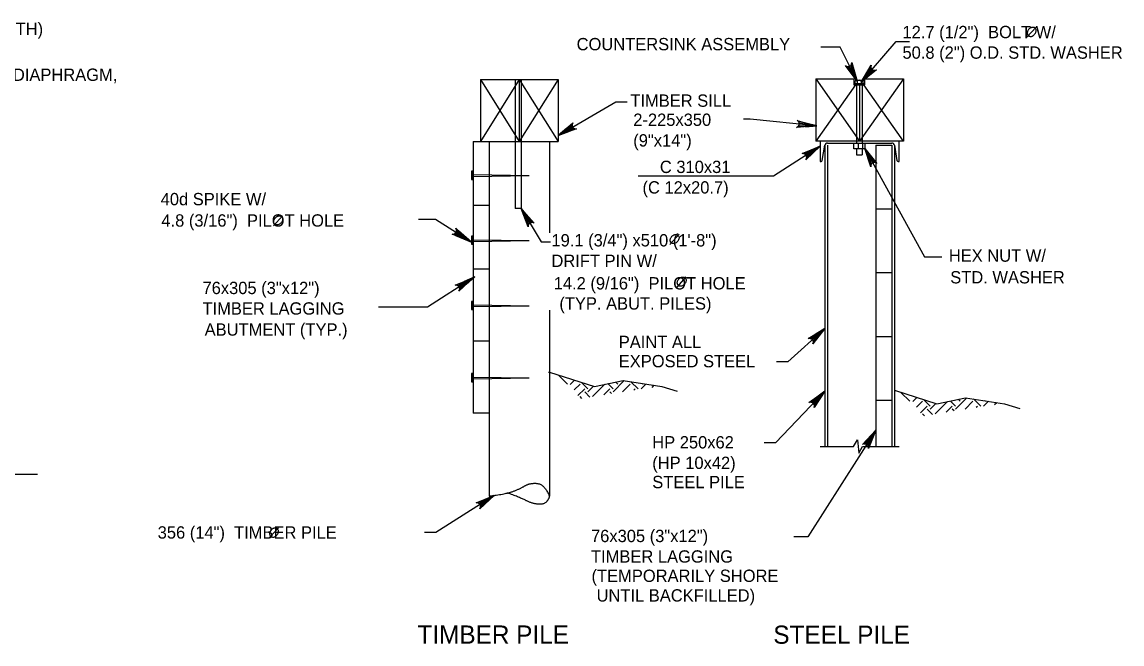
# Model space of a CAD drawing. Extents: x -13 to 81, y -176 to 0.
# Drawn here: x 47.78 to 58.49, y -37.68 to -31.62 of the extents above; entities that cross this region are included whole.
import ezdxf

# ---------------------------------------------------------------- set-up
doc = ezdxf.new("R2010")
doc.units = 0
for name, color, linetype in [('Level 3', 7, 'Continuous'), ('Level 4', 7, 'Continuous'), ('Level 5', 7, 'Continuous'), ('Level 52', 7, 'Continuous'), ('Level 8', 7, 'Continuous')]:
    doc.layers.add(name, color=color, linetype=linetype)

msp = doc.modelspace()

# ---------------------------------------------------------------- linework, layer by layer
at = {"layer": 'Level 3'}
for p, q in [((55.745, -31.865), (55.559, -31.865)), ((56.29, -31.812), (56.421, -31.812)), ((54.872, -32.566), (54.807, -32.566)), ((55.509, -32.633), (54.872, -32.566)), ((55.551, -32.831), (55.099, -33.124)), ((55.099, -33.124), (53.781, -33.124)), ((52.643, -33.438), (52.837, -33.762)), ((51.808, -33.545), (51.642, -33.545)), ((52.146, -33.758), (51.808, -33.545)), ((52.837, -33.762), (52.928, -33.762)), ((56.566, -33.908), (56.736, -33.908)), ((55.597, -35.217), (55.117, -35.72)), ((56.094, -35.597), (55.433, -36.635)), ((55.117, -35.72), (55.006, -35.72)), ((55.433, -36.635), (55.296, -36.635))]:
    msp.add_line(p, q, dxfattribs=at)
for points in [[(55.912, -32.197), (55.745, -31.865)], [(55.952, -32.208), (56.29, -31.812)], [(55.912, -32.197), (55.797, -32.046), (55.813, -32.054), (55.827, -32.056), (55.839, -32.052), (55.85, -32.044), (55.857, -32.032), (55.86, -32.015), (55.912, -32.197), (55.857, -32.032), (55.85, -32.044), (55.912, -32.197), (55.839, -32.052), (55.827, -32.056), (55.912, -32.197), (55.813, -32.054)], [(55.952, -32.208), (56.047, -32.043), (56.045, -32.06), (56.049, -32.074), (56.058, -32.084), (56.069, -32.09), (56.083, -32.093), (56.1, -32.088), (55.952, -32.208), (56.083, -32.093), (56.069, -32.09), (55.952, -32.208), (56.058, -32.084), (56.049, -32.074), (55.952, -32.208), (56.045, -32.06)], [(53.001, -32.727), (53.145, -32.602), (53.137, -32.618), (53.137, -32.633), (53.142, -32.645), (53.15, -32.654), (53.163, -32.661), (53.18, -32.663), (53.001, -32.727), (53.163, -32.661), (53.15, -32.654), (53.001, -32.727), (53.142, -32.645), (53.137, -32.633), (53.001, -32.727), (53.137, -32.618)], [(55.509, -32.633), (55.32, -32.649), (55.336, -32.64), (55.344, -32.628), (55.348, -32.616), (55.347, -32.604), (55.341, -32.59), (55.328, -32.579), (55.509, -32.633), (55.341, -32.59), (55.347, -32.604), (55.509, -32.633), (55.348, -32.616), (55.344, -32.628), (55.509, -32.633), (55.336, -32.64)], [(55.551, -32.831), (55.414, -32.962), (55.421, -32.946), (55.42, -32.931), (55.415, -32.919), (55.406, -32.91), (55.393, -32.904), (55.376, -32.903), (55.551, -32.831), (55.393, -32.904), (55.406, -32.91), (55.551, -32.831), (55.415, -32.919), (55.42, -32.931), (55.551, -32.831), (55.421, -32.946)], [(55.985, -32.852), (56.566, -33.908)], [(55.985, -32.852), (56.105, -32.998), (56.09, -32.99), (56.075, -32.99), (56.063, -32.994), (56.053, -33.002), (56.046, -33.014), (56.044, -33.032), (55.985, -32.852), (56.046, -33.014), (56.053, -33.002), (55.985, -32.852), (56.063, -32.994), (56.075, -32.99), (55.985, -32.852), (56.09, -32.99)], [(52.146, -33.758), (51.97, -33.689), (51.987, -33.688), (52, -33.681), (52.008, -33.672), (52.013, -33.66), (52.014, -33.645), (52.007, -33.629), (52.146, -33.758), (52.014, -33.645), (52.013, -33.66), (52.146, -33.758), (52.008, -33.672), (52, -33.681), (52.146, -33.758), (51.987, -33.688)], [(52.175, -34.112), (52.037, -34.243), (52.044, -34.227), (52.043, -34.212), (52.038, -34.201), (52.03, -34.191), (52.017, -34.185), (51.999, -34.184), (52.175, -34.112), (52.017, -34.185), (52.03, -34.191), (52.175, -34.112), (52.038, -34.201), (52.043, -34.212), (52.175, -34.112), (52.044, -34.227)], [(55.597, -34.605), (55.482, -34.756), (55.486, -34.739), (55.484, -34.725), (55.477, -34.714), (55.467, -34.706), (55.453, -34.702), (55.436, -34.704), (55.597, -34.605), (55.453, -34.702), (55.467, -34.706), (55.597, -34.605), (55.477, -34.714), (55.484, -34.725), (55.597, -34.605), (55.486, -34.739)], [(55.597, -35.217), (55.494, -35.376), (55.497, -35.359), (55.493, -35.345), (55.485, -35.334), (55.475, -35.327), (55.46, -35.324), (55.443, -35.328), (55.597, -35.217), (55.46, -35.324), (55.475, -35.327), (55.597, -35.217), (55.485, -35.334), (55.493, -35.345), (55.597, -35.217), (55.497, -35.359)], [(56.094, -35.597), (56.023, -35.773), (56.023, -35.755), (56.016, -35.742), (56.007, -35.734), (55.995, -35.729), (55.98, -35.728), (55.964, -35.735), (56.094, -35.597), (55.98, -35.728), (55.995, -35.729), (56.094, -35.597), (56.007, -35.734), (56.016, -35.742), (56.094, -35.597), (56.023, -35.755)], [(52.379, -36.231), (52.241, -36.361), (52.248, -36.345), (52.247, -36.33), (52.242, -36.319), (52.234, -36.309), (52.221, -36.303), (52.203, -36.302), (52.379, -36.231), (52.221, -36.303), (52.234, -36.309), (52.379, -36.231), (52.242, -36.319), (52.247, -36.33), (52.379, -36.231), (52.248, -36.345)]]:
    msp.add_lwpolyline(points, dxfattribs=at)
for points in [[(55.412, -32.605), (55.408, -32.641), (55.52, -32.634)], [(55.448, -32.876), (55.468, -32.907), (55.551, -32.831)], [(52.033, -33.654), (52.003, -33.701), (52.158, -33.766)], [(55.508, -35.284), (55.534, -35.31), (55.597, -35.217)], [(56.019, -35.68), (56.05, -35.7), (56.094, -35.597)]]:
    msp.add_lwpolyline(points, close=True, dxfattribs=at)
at = {"layer": 'Level 4'}
for p, q in [((57.564, -31.77), (57.654, -31.672)), ((50.232, -33.606), (50.321, -33.508)), ((54.09, -33.787), (54.179, -33.689)), ((54.159, -34.202), (54.248, -34.104)), ((50.191, -36.646), (50.281, -36.548))]:
    msp.add_line(p, q, dxfattribs=at)
for points in [[(57.644, -31.682), (57.637, -31.676), (57.63, -31.674), (57.622, -31.674), (57.616, -31.674), (57.608, -31.675), (57.6, -31.679), (57.594, -31.682), (57.584, -31.691), (57.576, -31.701), (57.571, -31.712), (57.568, -31.721), (57.567, -31.729), (57.568, -31.737), (57.571, -31.747), (57.575, -31.753), (57.583, -31.759), (57.594, -31.761), (57.608, -31.761), (57.624, -31.753), (57.636, -31.743), (57.646, -31.73), (57.652, -31.717), (57.654, -31.702), (57.651, -31.693), (57.645, -31.682)], [(50.312, -33.518), (50.305, -33.512), (50.298, -33.51), (50.289, -33.51), (50.284, -33.51), (50.276, -33.511), (50.268, -33.515), (50.262, -33.518), (50.252, -33.527), (50.243, -33.538), (50.238, -33.548), (50.235, -33.557), (50.234, -33.566), (50.235, -33.573), (50.239, -33.583), (50.243, -33.589), (50.25, -33.595), (50.262, -33.597), (50.275, -33.597), (50.292, -33.589), (50.304, -33.579), (50.313, -33.566), (50.319, -33.553), (50.321, -33.538), (50.319, -33.529), (50.312, -33.518)], [(54.17, -33.699), (54.163, -33.694), (54.156, -33.692), (54.147, -33.691), (54.142, -33.691), (54.133, -33.693), (54.125, -33.697), (54.12, -33.7), (54.109, -33.708), (54.101, -33.719), (54.096, -33.729), (54.093, -33.738), (54.092, -33.747), (54.093, -33.754), (54.097, -33.765), (54.101, -33.77), (54.108, -33.776), (54.12, -33.779), (54.133, -33.778), (54.15, -33.771), (54.162, -33.76), (54.171, -33.748), (54.177, -33.734), (54.179, -33.72), (54.177, -33.71), (54.17, -33.699)], [(54.239, -34.113), (54.232, -34.108), (54.225, -34.106), (54.216, -34.105), (54.211, -34.105), (54.203, -34.107), (54.194, -34.111), (54.189, -34.114), (54.178, -34.123), (54.17, -34.133), (54.165, -34.143), (54.162, -34.153), (54.161, -34.161), (54.162, -34.169), (54.166, -34.179), (54.17, -34.185), (54.177, -34.191), (54.189, -34.193), (54.202, -34.193), (54.219, -34.185), (54.231, -34.175), (54.24, -34.162), (54.246, -34.149), (54.248, -34.134), (54.246, -34.125), (54.239, -34.113)], [(50.271, -36.557), (50.264, -36.552), (50.257, -36.55), (50.249, -36.549), (50.243, -36.549), (50.235, -36.551), (50.227, -36.555), (50.221, -36.558), (50.211, -36.566), (50.203, -36.577), (50.198, -36.587), (50.195, -36.597), (50.194, -36.605), (50.195, -36.613), (50.198, -36.623), (50.202, -36.629), (50.21, -36.634), (50.221, -36.637), (50.235, -36.637), (50.251, -36.629), (50.264, -36.619), (50.273, -36.606), (50.279, -36.593), (50.281, -36.578), (50.278, -36.569), (50.272, -36.557)]]:
    msp.add_spline(points, degree=3, dxfattribs=at)
at = {"layer": 'Level 5'}
for p, q in [((52.245, -32.18), (53.001, -32.18)), ((52.246, -32.18), (52.246, -32.785)), ((52.623, -32.18), (52.246, -32.785)), ((52.246, -32.18), (52.623, -32.785)), ((52.585, -32.18), (52.585, -33.436)), ((52.623, -32.18), (53.001, -32.785)), ((53.001, -32.18), (52.623, -32.785)), ((52.623, -32.18), (52.623, -32.785)), ((52.643, -32.18), (52.643, -33.436)), ((53.001, -32.18), (53.001, -32.785)), ((55.509, -32.176), (55.935, -32.781)), ((55.509, -32.176), (55.509, -32.781)), ((55.509, -32.176), (55.664, -32.176)), ((55.509, -32.176), (55.881, -32.176)), ((55.881, -32.176), (55.881, -32.234)), ((55.881, -32.22), (55.985, -32.22)), ((55.892, -32.22), (55.892, -32.197)), ((55.962, -32.19), (55.902, -32.19)), ((55.912, -32.197), (55.912, -32.22)), ((56.362, -32.176), (55.935, -32.781)), ((55.952, -32.197), (55.952, -32.22)), ((55.971, -32.22), (55.971, -32.197)), ((55.985, -32.176), (56.362, -32.176)), ((56.362, -32.176), (56.362, -32.781)), ((55.895, -32.234), (55.509, -32.781)), ((55.904, -32.234), (55.904, -32.8)), ((55.935, -32.234), (55.935, -32.781)), ((55.962, -32.234), (55.962, -32.8)), ((56.362, -32.781), (55.977, -32.234)), ((53.001, -32.727), (53.564, -32.398)), ((53.564, -32.398), (53.675, -32.398)), ((52.175, -32.785), (52.175, -35.431)), ((52.175, -32.785), (52.33, -32.785)), ((52.246, -32.785), (53.001, -32.785)), ((52.33, -32.785), (52.33, -36.238)), ((52.917, -32.785), (52.917, -33.674)), ((56.362, -32.781), (55.509, -32.781)), ((55.551, -32.781), (55.551, -32.981)), ((55.572, -32.97), (55.597, -32.822)), ((55.597, -32.822), (55.597, -35.754)), ((55.623, -32.8), (56.248, -32.8)), ((55.623, -32.822), (55.623, -35.754)), ((55.904, -32.858), (55.904, -32.914)), ((55.925, -32.858), (55.925, -32.8)), ((55.962, -32.858), (55.962, -32.914)), ((55.968, -32.858), (55.968, -32.8)), ((56.094, -32.822), (56.094, -35.754)), ((56.094, -32.822), (56.249, -32.822)), ((56.249, -32.822), (56.249, -35.754)), ((56.274, -32.822), (56.274, -35.754)), ((56.274, -32.822), (56.299, -32.97)), ((56.32, -32.981), (56.32, -32.781)), ((55.904, -32.914), (55.962, -32.914)), ((55.551, -32.981), (55.56, -32.981)), ((56.312, -32.981), (56.32, -32.981)), ((52.175, -33.108), (52.72, -33.117)), ((52.175, -33.125), (52.72, -33.117)), ((52.175, -33.405), (52.33, -33.405)), ((52.643, -33.436), (52.585, -33.436)), ((56.094, -33.442), (56.249, -33.442)), ((52.175, -33.742), (52.72, -33.75)), ((52.175, -33.758), (52.72, -33.75)), ((52.175, -34.026), (52.33, -34.026)), ((52.175, -34.112), (51.732, -34.399)), ((56.094, -34.062), (56.249, -34.062)), ((51.732, -34.399), (51.254, -34.399)), ((52.175, -34.376), (52.72, -34.384)), ((52.175, -34.393), (52.72, -34.384)), ((52.917, -34.428), (52.917, -36.238)), ((55.597, -34.605), (55.237, -34.93)), ((56.094, -34.683), (56.249, -34.683)), ((52.33, -34.728), (52.175, -34.728)), ((55.237, -34.93), (55.126, -34.93)), ((52.175, -35.079), (52.72, -35.087)), ((52.175, -35.095), (52.72, -35.087)), ((53.092, -35.147), (53.005, -35.06)), ((53.12, -35.15), (53.161, -35.109)), ((53.157, -35.204), (53.215, -35.147)), ((53.194, -35.259), (53.261, -35.193)), ((53.291, -35.193), (53.229, -35.131)), ((53.291, -35.223), (53.346, -35.168)), ((53.337, -35.269), (53.457, -35.149)), ((53.446, -35.252), (53.505, -35.193)), ((53.536, -35.193), (53.486, -35.143)), ((53.536, -35.223), (53.646, -35.113)), ((53.582, -35.147), (53.562, -35.127)), ((53.629, -35.222), (53.704, -35.147)), ((53.78, -35.193), (53.711, -35.124)), ((53.738, -35.205), (53.75, -35.193)), ((53.809, -35.194), (53.857, -35.147)), ((53.826, -35.147), (53.82, -35.141)), ((53.917, -35.179), (53.936, -35.159)), ((53.233, -35.288), (53.215, -35.269)), ((53.312, -35.275), (53.261, -35.223)), ((53.521, -35.24), (53.505, -35.223)), ((56.094, -35.303), (56.249, -35.303)), ((56.425, -35.315), (56.338, -35.228)), ((56.453, -35.318), (56.494, -35.278)), ((56.49, -35.373), (56.548, -35.315)), ((56.624, -35.361), (56.562, -35.3)), ((56.67, -35.438), (56.79, -35.318)), ((56.869, -35.361), (56.819, -35.312)), ((56.869, -35.392), (56.979, -35.282)), ((56.915, -35.315), (56.895, -35.295)), ((56.962, -35.39), (57.037, -35.315)), ((57.114, -35.361), (57.044, -35.292)), ((57.143, -35.363), (57.19, -35.315)), ((57.16, -35.315), (57.153, -35.309)), ((52.33, -35.431), (52.175, -35.431)), ((56.527, -35.427), (56.594, -35.361)), ((56.645, -35.443), (56.594, -35.392)), ((56.624, -35.392), (56.679, -35.337)), ((56.779, -35.421), (56.838, -35.361)), ((56.855, -35.408), (56.838, -35.392)), ((57.071, -35.373), (57.083, -35.361)), ((57.25, -35.347), (57.27, -35.328)), ((56.566, -35.456), (56.548, -35.438)), ((55.551, -35.754), (55.876, -35.754)), ((55.876, -35.754), (55.914, -35.691)), ((55.914, -35.691), (55.927, -35.819)), ((55.927, -35.819), (55.963, -35.754)), ((55.963, -35.754), (56.32, -35.754)), ((52.379, -36.231), (51.813, -36.594)), ((51.813, -36.594), (51.702, -36.594))]:
    msp.add_line(p, q, dxfattribs=at)
for points in [[(55.881, -32.234), (55.985, -32.234), (55.985, -32.176)], [(52.907, -35.03), (52.917, -35.032), (53.355, -35.171), (53.634, -35.111), (54.012, -35.171), (54.161, -35.216)], [(56.274, -35.208), (56.688, -35.34), (56.967, -35.28), (57.345, -35.34), (57.494, -35.385)]]:
    msp.add_lwpolyline(points, dxfattribs=at)
for points in [[(53.106, -32.687), (53.088, -32.655), (53.001, -32.727)], [(55.881, -32.8), (55.985, -32.8), (55.985, -32.858), (55.881, -32.858)], [(52.159, -33.074), (52.159, -33.154), (52.175, -33.154), (52.175, -33.074)], [(52.159, -33.707), (52.159, -33.786), (52.175, -33.786), (52.175, -33.707)], [(52.087, -34.147), (52.107, -34.178), (52.19, -34.102)], [(52.159, -34.342), (52.159, -34.421), (52.175, -34.421), (52.175, -34.342)], [(55.503, -34.666), (55.528, -34.693), (55.597, -34.605)], [(52.159, -35.045), (52.159, -35.124), (52.175, -35.124), (52.175, -35.045)], [(52.268, -36.28), (52.288, -36.311), (52.371, -36.236)]]:
    msp.add_lwpolyline(points, close=True, dxfattribs=at)
for centre, radius, start, end in [((55.902, -32.201), 0.011, 88.1729, 158.7131), ((55.902, -32.201), 0.011, 21.2869, 88.1729), ((55.932, -32.221), 0.0316, 51.05, 128.95), ((55.962, -32.2), 0.0101, 17.4518, 162.5482), ((55.623, -32.826), 0.0262, 90.0372, 170.4628), ((56.248, -32.826), 0.0261, 9.5, 90), ((55.56, -32.968), 0.0131, 270.2863, 350.2137), ((56.312, -32.968), 0.0131, 189.5372, 269.9628)]:
    msp.add_arc(centre, radius, start, end, dxfattribs=at)
msp.add_open_spline([(52.33, -36.238), (52.49, -36.218), (52.624, -36.171), (52.727, -36.108), (52.867, -36.121), (52.917, -36.238)], degree=2, dxfattribs=at)
at = {"layer": 'Level 52'}
msp.add_lwpolyline([(52.643, -33.438), (52.769, -33.58), (52.753, -33.573), (52.738, -33.573), (52.726, -33.577), (52.717, -33.586), (52.71, -33.598), (52.709, -33.616), (52.643, -33.438), (52.71, -33.598), (52.717, -33.586), (52.643, -33.438), (52.726, -33.577), (52.738, -33.573), (52.643, -33.438), (52.753, -33.573)], dxfattribs=at)
at = {"layer": 'Level 8'}
msp.add_line((44.107, -36.024), (47.935, -36.024), dxfattribs=at)
msp.add_open_spline([(52.917, -36.238), (52.898, -36.317), (52.758, -36.317), (52.639, -36.255), (52.509, -36.206)], degree=2, dxfattribs=at)

# ---------------------------------------------------------------- texts
at = {"layer": 'Level 3'}
for s, height, p in [('L 19.1 (3/4")  LAG SCREW (LENGTH OF LAG SCREW = 175 (7")+ BEAM WIDTH)', 0.12, (42.071, -31.748)), ('12.7 (1/2")  BOLT W/', 0.12, (56.353, -31.779)), ('COUNTERSINK ASSEMBLY', 0.12, (53.182, -31.897)), ('50.8 (2") O.D. STD. WASHER', 0.12, (56.353, -31.979)), ('14.3 (9/16")  FOR RED MAPLE & 12.7 (1/2")  FOR YELLOW POPLAR IN THE DIAPHRAGM, ', 0.12, (42.071, -32.195)), ('TIMBER SILL', 0.12, (53.705, -32.447)), ('2-225x350', 0.12, (53.733, -32.633)), ('(9"x14")', 0.12, (53.733, -32.834)), ('C 310x31', 0.12, (53.992, -33.092)), ('(C 12x20.7)', 0.12, (53.823, -33.292)), ('40d SPIKE W/', 0.12, (49.134, -33.406)), ('4.8 (3/16")  PILOT HOLE', 0.12, (49.141, -33.614)), ('19.1 (3/4") x510 (1\'-8")', 0.12, (52.937, -33.807)), ('DRIFT PIN W/', 0.12, (52.937, -34.007)), ('HEX NUT W/', 0.12, (56.804, -33.956)), ('76x305 (3"x12")', 0.12, (49.541, -34.271)), ('14.2 (9/16")  PILOT HOLE', 0.12, (52.959, -34.226)), ('STD. WASHER', 0.12, (56.818, -34.167)), ('TIMBER LAGGING', 0.12, (49.541, -34.471)), ('(TYP. ABUT. PILES)', 0.12, (53.014, -34.422)), ('ABUTMENT (TYP.)', 0.12, (49.562, -34.676)), ('PAINT ALL', 0.12, (53.592, -34.797)), ('EXPOSED STEEL', 0.12, (53.592, -34.984)), ('HP 250x62', 0.12, (53.918, -35.774)), ('(HP 10x42)', 0.12, (53.918, -35.974)), ('STEEL PILE', 0.12, (53.918, -36.161)), ('356 (14")  TIMBER PILE', 0.12, (49.105, -36.652)), ('76x305 (3"x12")', 0.12, (53.322, -36.686)), ('TIMBER LAGGING', 0.12, (53.322, -36.886)), ('(TEMPORARILY SHORE ', 0.12, (53.327, -37.074)), ('UNTIL BACKFILLED)', 0.12, (53.376, -37.265)), ('TIMBER PILE', 0.17717, (51.633, -37.675)), ('STEEL PILE', 0.1772, (55.096, -37.676))]:
    msp.add_text(s, height=height, dxfattribs=at).set_placement(p)

doc.saveas('drawing.dxf')
